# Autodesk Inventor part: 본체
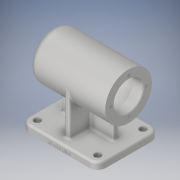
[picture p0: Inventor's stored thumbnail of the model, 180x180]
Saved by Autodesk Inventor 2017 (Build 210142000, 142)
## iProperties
Part Number: 본체
Material: 알루미늄 6061
Document SubType Name: Modeling
Designer: 00-00
Density: 2.7 g/cm^3
Appearance: 알루미늄 - 평지
Mass: 1026.28 g
Surface Area: 757.984 cm^2
Volume: 380.103 cm^3
Author: 00-00
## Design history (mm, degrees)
sketch "스케치1"
  geometry: L1 (-56, 45)-(56, 45); L2 (56, 45)-(56, -45); L3 (56, -45)-(-56, -45); L4 (-56, -45)-(-56, 45); L5 (-56, 45)-(56, -45); L6 (56, 45)-(-56, -45); 1 further point
  constraints: 12 end point, 2 midpoint, 2 parallel, 1 horizontal, 1 perpendicular
  dimensions: "d0" = 112 distance of L2.end L3.end; "d1" = 90 distance of L1.end L2.end
extrude "돌출1" new body sketch "스케치1" distance "d2" = 10; taper "d3" = 0 deg
sketch "스케치2"
  geometry: L1 (0, 45)-(-74, 45); C1 r 34 at (-74, 45)
  constraints: 2 end point, 1 centre point, 1 coincident, 1 horizontal
  dimensions: "d4" = 74 distance of L1.start L1.end; "d5" = 68 diameter of C1
extrude "돌출2" join sketch "스케치2" distance "d6" = 112; taper "d7" = 0 deg
sketch "스케치3"
  geometry: L1 (38, -4)-(-38, -4); L2 (56, -45)-(56, 45) reference; L3 (-56, 45)-(-56, -45) reference; L4 (-38, -4)-(-38, 4); L5 (-38, 4)-(38, 4); L6 (38, 4)-(38, -4); L7 (-4, 34)-(4, 34); L8 (4, 34)-(4, -34); L9 (4, -34)-(-4, -34); L10 (-4, -34)-(-4, 34); L11 (-4, 34)-(4, -34); L12 (4, 34)-(-4, -34); 1 further point
  constraints: 20 end point, 3 perpendicular, 2 horizontal, 2 midpoint, 2 parallel, 1 vertical
  dimensions: "d8" = 18 distance from line of L2 L1.start; "d9" = 18 distance from line of L3 L1.end; "d10" = 4 distance from line of point (0, 0) L1; "d11" = 8 distance of L1.end L4.end; "d12" = 8 distance of L8.end L9.end; "d13" = 68 distance of L7.end L8.end
extrude "돌출3" join sketch "스케치3" stored distance "d14" = 112; taper "d15" = 0 deg
sketch "스케치4"
  geometry: C1 r 34 at (0, 0) reference; C2 r 21 at (0, 0); 1 further point
  constraints: 1 centre point, 1 coincident
  dimensions: "d16" = 42 diameter of C2
extrude "돌출4" cut sketch "스케치4" distance "d17" = 81; taper "d18" = 0 deg
node "작업 평면1"
sketch "스케치5"
  geometry: C1 r 34 at (0, 0) reference; C2 r 24 at (0, 0); 1 further point
  constraints: 1 centre point, 1 coincident
  dimensions: "d20" = 48 diameter of C2
extrude "돌출5" cut sketch "스케치5" distance "d21" = 54; taper "d22" = 0 deg
sketch "스케치6"
  geometry: C1 r 34 at (0, 0) reference; C2 r 17.5 at (0, 0); 1 further point
  constraints: 1 centre point, 1 coincident
  dimensions: "d23" = 35 diameter of C2
extrude "돌출6" cut sketch "스케치6" distance "d24" = 18; taper "d25" = 0 deg
sketch "스케치7"
  geometry: C1 r 34 at (0, 0) reference; C2 r 16 at (0, 0); 1 further point
  constraints: 1 centre point, 1 coincident
  dimensions: "d26" = 32 diameter of C2
extrude "돌출7" cut sketch "스케치7" distance "d27" = 4; taper "d28" = 0 deg
sketch "스케치8"
  geometry: C1 r 34 at (0, 0) reference; C2 r 10.5 at (0, 0); 1 further point
  constraints: 1 centre point, 1 coincident
  dimensions: "d29" = 21 diameter of C2
extrude "돌출8" cut sketch "스케치8" distance "d30" = 3; taper "d31" = 0 deg
fillet "모깎기1" dims "d32" = 10
fillet "모깎기2" dims "d33" = 12
fillet "모깎기3" dims "d34" = 3
chamfer "모따기1" distance "d35" = 1; stored, may be unused: second distance "d36" = 2, angle "d37" = 45 deg
fillet "모깎기4" dims "d38" = 3
fillet "모깎기5" dims "d39" = 0.3
fillet "모깎기6" dims "d40" = 3
sketch "스케치9"
  geometry: A1 r 9 centre (-44, 33) between (-44, 42) and (-53, 33) reference; A2 r 9 centre (44, 33) between (53, 33) and (44, 42) reference; A3 r 9 centre (-44, -33) between (-53, -33) and (-44, -42) reference; A4 r 9 centre (44, -33) between (44, -42) and (53, -33) reference; 5 further points
  constraints: 4 coincident
hole "구멍1" sketch "스케치9" at (-44, 33), (44, 33), (44, -33), (-44, -33) diameter "d41" = 5.5; stored, may be unused: countersink angle "d45" = 90 deg, drill point angle "d47" = 118 deg; dims "d42" = 6, "d43" = 9.5, "d44" = 5.4, "d46" = 8
sketch "스케치10" dims "d48" = 52
  geometry: C1 r 34 at (0, 0) reference; 6 further points
  constraints: 2 horizontal alignment, 1 coincident, 7 other
  dimensions: "d51" = 360 deg dimension on C1.centre point (-26, 0) (derived)
hole "구멍2" sketch "스케치10" at (-26, 0), (0, -26), (26, 0), (0, 26) diameter "d53" = 3.242; stored, may be unused: countersink angle "d57" = 90 deg, drill point angle "d59" = 118 deg; dims "d54" = 8, "d55" = 9.5, "d56" = 5.4, "d58" = 11
sketch "스케치11"
  geometry: L1 (100, 0)-(100, 7) reference; L2 (88, 0)-(0, 0) reference; 2 further points
  constraints: 1 other
  dimensions: "d61" = 56 distance from line of L1 point (44, 3); "d62" = 3 distance from line of L2 point (44, 3)
feature "엠보싱1" sketch "스케치11" dims "d0" = 112, "d1" = 90, "d8" = 18, "d9" = 18, "d10" = 4, "d11" = 8, "d63" = 0.5, "d64" = 0
node "솔리드1"
other parameters: "d19" = -15
